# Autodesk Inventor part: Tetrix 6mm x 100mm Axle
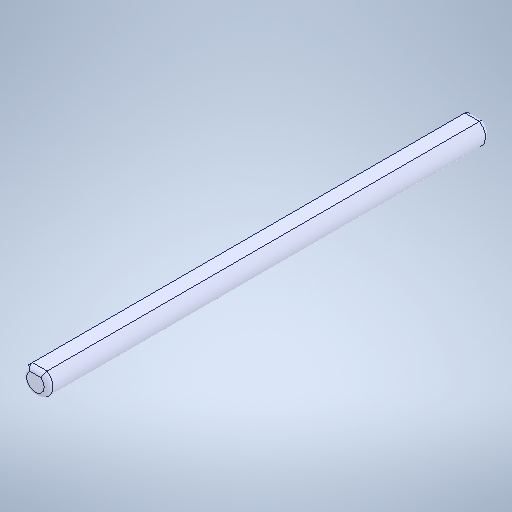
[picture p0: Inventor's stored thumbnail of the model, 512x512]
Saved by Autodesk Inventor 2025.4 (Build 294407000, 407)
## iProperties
Created: 2021-10
Part Number: Tetrix 6mm x 100mm Axle
Material: Genérico
Document SubType Name: Modeling
Designer: usuario
Density: 1 g/cm^3
Appearance: Valor por defecto
Author: usuario
Sending System: SolidWorks 2016
Last Author: LENOVO
Last Saved: 2021-10-26
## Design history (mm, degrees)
fillet "Fillet1"
node "Plane1"
node "Sólido1"
